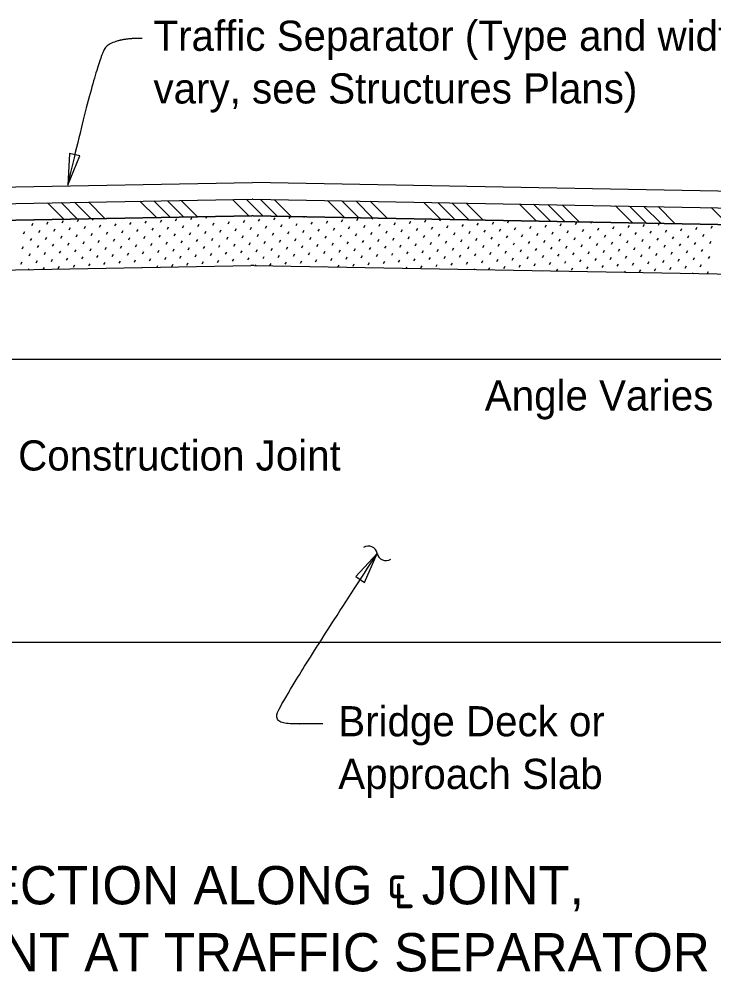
# Model space of a CAD drawing. Extents: x -7.9 to 27, y -3.1 to 14.6.
# Drawn here: x 7.115 to 8.858, y 7.064 to 9.452 of the extents above; entities that cross this region are included whole.
import ezdxf

# ---------------------------------------------------------------- set-up
doc = ezdxf.new("R2010")
doc.units = 0
for name, color, linetype in [('Border', 7, 'Continuous'), ('Patterning', 7, 'Continuous'), ('PlotBorder_dp', 7, 'Continuous'), ('SupstrConc_h', 7, 'Continuous'), ('TextMisc', 7, 'Continuous')]:
    doc.layers.add(name, color=color, linetype=linetype)

msp = doc.modelspace()

# ---------------------------------------------------------------- linework, layer by layer
at = {"layer": 'Patterning'}
for p, q in [((6.7193, 9.0243), (7.7, 9.0424)), ((9.1446, 9.0156), (7.7, 9.0424)), ((5.2585, 7.8906), (10.1444, 7.8906))]:
    msp.add_line(p, q, dxfattribs=at)
at = {"layer": 'PlotBorder_dp'}
for points in [[(7.2366, 9.0361), (7.2671, 9.1092), (7.2413, 9.1152)], [(8.013, 8.1128), (7.9591, 8.0547), (7.9813, 8.0402)]]:
    msp.add_lwpolyline(points, close=True, dxfattribs=at)
for centre, start, end in [((7.9909, 8.1087), 10.958, 122.6852), ((8.0347, 8.1172), 190.958, 302.6852)]:
    msp.add_arc(centre, 0.0224, start, end, dxfattribs=at)
for points in [[(7.4236, 9.4037), (7.3532, 9.4037), (7.3114, 9.3597), (7.2366, 9.0362)], [(7.8761, 7.6857), (7.8344, 7.6857), (7.7607, 7.6857), (7.7607, 7.7274), (8.013, 8.1128)]]:
    msp.add_open_spline(points, degree=2, dxfattribs=at)
at = {"layer": 'SupstrConc_h'}
msp.add_lwpolyline([(9.1821, 8.599), (5.5686, 8.599)], dxfattribs=at)
at = {"layer": 'TextMisc'}
for p, q in [((6.2769, 8.9744), (7.6992, 9.0007)), ((7.1861, 8.9912), (7.227, 8.9503)), ((7.2204, 8.9919), (7.2614, 8.9509)), ((7.2548, 8.9925), (7.2957, 8.9515)), ((7.2892, 8.9931), (7.3301, 8.9522)), ((7.4179, 8.9955), (7.4589, 8.9546)), ((7.4523, 8.9962), (7.4932, 8.9552)), ((7.4866, 8.9968), (7.5276, 8.9558)), ((7.521, 8.9974), (7.5619, 8.9565)), ((7.6498, 8.9998), (7.6907, 8.9589)), ((7.6841, 9.0004), (7.726, 8.9586)), ((7.7008, 9.0007), (9.1231, 8.9744)), ((7.7192, 9.0004), (7.7617, 8.9579)), ((7.7548, 8.9997), (7.7973, 8.9572)), ((7.8885, 8.9972), (7.931, 8.9548)), ((7.9241, 8.9966), (7.9666, 8.9541)), ((7.9598, 8.9959), (8.0023, 8.9534)), ((7.9954, 8.9953), (8.0379, 8.9528)), ((8.1291, 8.9928), (8.1716, 8.9503)), ((8.1647, 8.9921), (8.2072, 8.9496)), ((8.2004, 8.9915), (8.2429, 8.949)), ((8.236, 8.9908), (8.2785, 8.9483)), ((8.3697, 8.9883), (8.4122, 8.9458)), ((8.4053, 8.9877), (8.4478, 8.9452)), ((8.441, 8.987), (8.4835, 8.9445)), ((8.4767, 8.9863), (8.5191, 8.9439)), ((8.6103, 8.9839), (8.6528, 8.9414)), ((8.6459, 8.9832), (8.6884, 8.9407)), ((8.6816, 8.9826), (8.7241, 8.9401)), ((8.7173, 8.9819), (8.7597, 8.9394)), ((7.6985, 8.959), (6.2985, 8.9331)), ((6.2985, 8.9331), (7.6985, 8.959)), ((7.5836, 8.953), (7.5858, 8.9569)), ((7.6217, 8.9563), (7.6225, 8.9576)), ((9.1015, 8.9331), (7.7015, 8.959)), ((7.7015, 8.959), (9.1015, 8.9331)), ((7.7918, 8.9518), (7.795, 8.9573)), ((7.83, 8.955), (7.8309, 8.9566)), ((8.8509, 8.9794), (8.8934, 8.9369)), ((7.1464, 8.9348), (7.1497, 8.9404)), ((7.1846, 8.9381), (7.1878, 8.9437)), ((7.2227, 8.9413), (7.226, 8.9469)), ((7.2609, 8.9446), (7.2641, 8.9502)), ((7.2783, 8.9271), (7.2816, 8.9327)), ((7.299, 8.9478), (7.3013, 8.9516)), ((7.3165, 8.9303), (7.3197, 8.9359)), ((7.3372, 8.951), (7.3379, 8.9523)), ((7.3547, 8.9336), (7.3579, 8.9392)), ((7.3928, 8.9368), (7.3961, 8.9424)), ((7.431, 8.9401), (7.4342, 8.9457)), ((7.4691, 8.9433), (7.4724, 8.9489)), ((7.5073, 8.9465), (7.5105, 8.9521)), ((7.5247, 8.9291), (7.528, 8.9347)), ((7.5454, 8.9498), (7.5487, 8.9554)), ((7.5629, 8.9323), (7.5661, 8.9379)), ((7.601, 8.9356), (7.6043, 8.9412)), ((7.6392, 8.9388), (7.6424, 8.9444)), ((7.6773, 8.9421), (7.6806, 8.9476)), ((7.7155, 8.9453), (7.7187, 8.9509)), ((7.733, 8.9278), (7.7362, 8.9334)), ((7.7537, 8.9485), (7.7569, 8.9541)), ((7.7711, 8.9311), (7.7744, 8.9367)), ((7.8093, 8.9343), (7.8125, 8.9399)), ((7.8474, 8.9376), (7.8507, 8.9432)), ((7.8856, 8.9408), (7.8888, 8.9464)), ((7.9237, 8.944), (7.927, 8.9496)), ((7.9619, 8.9473), (7.9651, 8.9529)), ((7.9793, 8.9298), (7.9826, 8.9354)), ((8, 8.9505), (8.0017, 8.9534)), ((8.0175, 8.9331), (8.0207, 8.9387)), ((8.0557, 8.9363), (8.0589, 8.9419)), ((8.0938, 8.9395), (8.097, 8.9451)), ((8.132, 8.9428), (8.1352, 8.9484)), ((8.1701, 8.946), (8.1726, 8.9503)), ((8.1876, 8.9286), (8.1908, 8.9342)), ((8.2083, 8.9493), (8.2085, 8.9496)), ((8.2257, 8.9318), (8.229, 8.9374)), ((8.2639, 8.9351), (8.2671, 8.9407)), ((8.302, 8.9383), (8.3053, 8.9439)), ((8.3402, 8.9415), (8.3434, 8.9471)), ((8.3783, 8.9448), (8.3793, 8.9464)), ((8.3958, 8.9273), (8.399, 8.9329)), ((8.434, 8.9306), (8.4372, 8.9362)), ((8.4721, 8.9338), (8.4753, 8.9394)), ((8.5103, 8.937), (8.5135, 8.9426)), ((8.5484, 8.9403), (8.5501, 8.9433)), ((8.6422, 8.9293), (8.6454, 8.9349)), ((8.6803, 8.9325), (8.6836, 8.9381)), ((8.7185, 8.9358), (8.721, 8.9401)), ((8.7566, 8.939), (8.7569, 8.9394)), ((8.8504, 8.9281), (8.8536, 8.9337)), ((7.1257, 8.9141), (7.129, 8.9197)), ((7.1639, 8.9174), (7.1671, 8.923)), ((7.202, 8.9206), (7.2053, 8.9262)), ((7.2195, 8.9032), (7.2227, 8.9088)), ((7.2402, 8.9239), (7.2434, 8.9295)), ((7.2577, 8.9064), (7.2609, 8.912)), ((7.2958, 8.9096), (7.299, 8.9152)), ((7.334, 8.9129), (7.3372, 8.9185)), ((7.3721, 8.9161), (7.3754, 8.9217)), ((7.4103, 8.9194), (7.4135, 8.925)), ((7.4484, 8.9226), (7.4517, 8.9282)), ((7.4659, 8.9051), (7.4691, 8.9107)), ((7.4866, 8.9258), (7.4898, 8.9314)), ((7.504, 8.9084), (7.5073, 8.914)), ((7.5422, 8.9116), (7.5454, 8.9172)), ((7.5803, 8.9149), (7.5836, 8.9205)), ((7.6185, 8.9181), (7.6217, 8.9237)), ((7.6567, 8.9214), (7.6599, 8.927)), ((7.6741, 8.9039), (7.6773, 8.9095)), ((7.6948, 8.9246), (7.698, 8.9302)), ((7.7123, 8.9071), (7.7155, 8.9127)), ((7.7504, 8.9104), (7.7537, 8.916)), ((7.7886, 8.9136), (7.7918, 8.9192)), ((7.8267, 8.9169), (7.83, 8.9225)), ((7.8649, 8.9201), (7.8681, 8.9257)), ((7.903, 8.9233), (7.9063, 8.9289)), ((7.9205, 8.9059), (7.9237, 8.9115)), ((7.9412, 8.9266), (7.9444, 8.9322)), ((7.9586, 8.9091), (7.9619, 8.9147)), ((7.9968, 8.9124), (8, 8.918)), ((8.035, 8.9156), (8.0382, 8.9212)), ((8.0731, 8.9188), (8.0763, 8.9244)), ((8.1113, 8.9221), (8.1145, 8.9277)), ((8.1287, 8.9046), (8.132, 8.9102)), ((8.1494, 8.9253), (8.1527, 8.9309)), ((8.1669, 8.9079), (8.1701, 8.9135)), ((8.205, 8.9111), (8.2083, 8.9167)), ((8.2432, 8.9144), (8.2464, 8.92)), ((8.2813, 8.9176), (8.2846, 8.9232)), ((8.3195, 8.9208), (8.3227, 8.9264)), ((8.3369, 8.9034), (8.3402, 8.909)), ((8.3576, 8.9241), (8.3609, 8.9297)), ((8.3751, 8.9066), (8.3783, 8.9122)), ((8.4133, 8.9099), (8.4165, 8.9155)), ((8.4514, 8.9131), (8.4546, 8.9187)), ((8.4896, 8.9163), (8.4928, 8.9219)), ((8.5277, 8.9196), (8.531, 8.9252)), ((8.5659, 8.9228), (8.5691, 8.9284)), ((8.5833, 8.9054), (8.5866, 8.911)), ((8.604, 8.9261), (8.6073, 8.9317)), ((8.6215, 8.9086), (8.6247, 8.9142)), ((8.6596, 8.9119), (8.6629, 8.9174)), ((8.6978, 8.9151), (8.701, 8.9207)), ((8.7359, 8.9183), (8.7392, 8.9239)), ((8.7741, 8.9216), (8.7773, 8.9272)), ((8.7916, 8.9041), (8.7948, 8.9097)), ((8.8123, 8.9248), (8.8155, 8.9304)), ((8.8297, 8.9074), (8.833, 8.913)), ((7.1432, 8.8967), (7.1464, 8.9023)), ((7.1606, 8.8792), (7.1639, 8.8848)), ((7.1813, 8.8999), (7.1846, 8.9055)), ((7.1988, 8.8825), (7.202, 8.8881)), ((7.237, 8.8857), (7.2402, 8.8913)), ((7.2751, 8.8889), (7.2783, 8.8945)), ((7.3133, 8.8922), (7.3165, 8.8978)), ((7.3514, 8.8954), (7.3547, 8.901)), ((7.3896, 8.8987), (7.3928, 8.9043)), ((7.407, 8.8812), (7.4103, 8.8868)), ((7.4277, 8.9019), (7.431, 8.9075)), ((7.4452, 8.8845), (7.4484, 8.89)), ((7.4833, 8.8877), (7.4866, 8.8933)), ((7.5215, 8.8909), (7.5247, 8.8965)), ((7.5596, 8.8942), (7.5629, 8.8998)), ((7.5978, 8.8974), (7.601, 8.903)), ((7.6153, 8.88), (7.6185, 8.8856)), ((7.636, 8.9007), (7.6392, 8.9063)), ((7.6534, 8.8832), (7.6567, 8.8888)), ((7.6916, 8.8864), (7.6948, 8.892)), ((7.7297, 8.8897), (7.733, 8.8953)), ((7.7679, 8.8929), (7.7711, 8.8985)), ((7.806, 8.8962), (7.8093, 8.9018)), ((7.8442, 8.8994), (7.8474, 8.905)), ((7.8616, 8.8819), (7.8649, 8.8875)), ((7.8823, 8.9026), (7.8856, 8.9082)), ((7.8998, 8.8852), (7.903, 8.8908)), ((7.9379, 8.8884), (7.9412, 8.894)), ((7.9761, 8.8917), (7.9793, 8.8973)), ((8.0143, 8.8949), (8.0175, 8.9005)), ((8.0524, 8.8982), (8.0557, 8.9037)), ((8.0699, 8.8807), (8.0731, 8.8863)), ((8.0906, 8.9014), (8.0938, 8.907)), ((8.108, 8.8839), (8.1113, 8.8895)), ((8.1462, 8.8872), (8.1494, 8.8928)), ((8.1843, 8.8904), (8.1876, 8.896)), ((8.2225, 8.8937), (8.2257, 8.8993)), ((8.2606, 8.8969), (8.2639, 8.9025)), ((8.2781, 8.8794), (8.2813, 8.885)), ((8.2988, 8.9001), (8.302, 8.9057)), ((8.3162, 8.8827), (8.3195, 8.8883)), ((8.3544, 8.8859), (8.3576, 8.8915)), ((8.3926, 8.8892), (8.3958, 8.8948)), ((8.4307, 8.8924), (8.434, 8.898)), ((8.4689, 8.8956), (8.4721, 8.9012)), ((8.507, 8.8989), (8.5103, 8.9045)), ((8.5245, 8.8814), (8.5277, 8.887)), ((8.5452, 8.9021), (8.5484, 8.9077)), ((8.5626, 8.8847), (8.5659, 8.8903)), ((8.6008, 8.8879), (8.604, 8.8935)), ((8.6389, 8.8912), (8.6422, 8.8968)), ((8.6771, 8.8944), (8.6803, 8.9)), ((8.7152, 8.8976), (8.7185, 8.9032)), ((8.7327, 8.8802), (8.7359, 8.8858)), ((8.7534, 8.9009), (8.7566, 8.9065)), ((8.7709, 8.8834), (8.7741, 8.889)), ((8.809, 8.8867), (8.8123, 8.8923)), ((8.8472, 8.8899), (8.8504, 8.8955)), ((7.1225, 8.876), (7.1257, 8.8816)), ((7.1399, 8.8585), (7.1432, 8.8641)), ((7.1781, 8.8618), (7.1813, 8.8674)), ((7.2163, 8.865), (7.2195, 8.8706)), ((7.2544, 8.8682), (7.2577, 8.8738)), ((7.2926, 8.8715), (7.2958, 8.8771)), ((7.3307, 8.8747), (7.334, 8.8803)), ((7.3482, 8.8573), (7.3514, 8.8629)), ((7.3689, 8.878), (7.3721, 8.8836)), ((7.3863, 8.8605), (7.3896, 8.8661)), ((7.4245, 8.8638), (7.4277, 8.8694)), ((7.4626, 8.867), (7.4659, 8.8726)), ((7.5008, 8.8702), (7.504, 8.8758)), ((7.5389, 8.8735), (7.5422, 8.8791)), ((7.5564, 8.856), (7.5596, 8.8616)), ((7.5771, 8.8767), (7.5803, 8.8823)), ((7.5946, 8.8593), (7.5978, 8.8649)), ((7.6327, 8.8625), (7.636, 8.8681)), ((7.6709, 8.8657), (7.6741, 8.8713)), ((7.709, 8.869), (7.7123, 8.8746)), ((7.7472, 8.8722), (7.7504, 8.8778)), ((7.7853, 8.8755), (7.7886, 8.8811)), ((7.8028, 8.858), (7.806, 8.8636)), ((7.8235, 8.8787), (7.8267, 8.8843)), ((7.8409, 8.8612), (7.8442, 8.8668)), ((7.8791, 8.8645), (7.8823, 8.8701)), ((7.9172, 8.8677), (7.9205, 8.8733)), ((7.9554, 8.871), (7.9586, 8.8766)), ((7.9936, 8.8742), (7.9968, 8.8798)), ((8.011, 8.8568), (8.0143, 8.8624)), ((8.0317, 8.8775), (8.035, 8.8831)), ((8.0492, 8.86), (8.0524, 8.8656)), ((8.0873, 8.8632), (8.0906, 8.8688)), ((8.1255, 8.8665), (8.1287, 8.8721)), ((8.1636, 8.8697), (8.1669, 8.8753)), ((8.2018, 8.873), (8.205, 8.8786)), ((8.2192, 8.8555), (8.2225, 8.8611)), ((8.2399, 8.8762), (8.2432, 8.8818)), ((8.2574, 8.8587), (8.2606, 8.8643)), ((8.2956, 8.862), (8.2988, 8.8676)), ((8.3337, 8.8652), (8.3369, 8.8708)), ((8.3719, 8.8685), (8.3751, 8.8741)), ((8.41, 8.8717), (8.4133, 8.8773)), ((8.4482, 8.8749), (8.4514, 8.8805)), ((8.4656, 8.8575), (8.4689, 8.8631)), ((8.4863, 8.8782), (8.4896, 8.8838)), ((8.5038, 8.8607), (8.507, 8.8663)), ((8.5419, 8.864), (8.5452, 8.8696)), ((8.5801, 8.8672), (8.5833, 8.8728)), ((8.6182, 8.8705), (8.6215, 8.8761)), ((8.6564, 8.8737), (8.6596, 8.8793)), ((8.6739, 8.8562), (8.6771, 8.8618)), ((8.6946, 8.8769), (8.6978, 8.8825)), ((8.712, 8.8595), (8.7152, 8.8651)), ((8.7502, 8.8627), (8.7534, 8.8683)), ((8.7883, 8.866), (8.7916, 8.8716)), ((8.8265, 8.8692), (8.8297, 8.8748)), ((7.1192, 8.8378), (7.1225, 8.8434)), ((7.1574, 8.8411), (7.1606, 8.8467)), ((7.1956, 8.8443), (7.1988, 8.8499)), ((7.2337, 8.8475), (7.237, 8.8531)), ((7.2719, 8.8508), (7.2751, 8.8564)), ((7.2893, 8.8333), (7.2926, 8.8389)), ((7.31, 8.854), (7.3133, 8.8596)), ((7.3275, 8.8366), (7.3307, 8.8422)), ((7.3656, 8.8398), (7.3689, 8.8454)), ((7.4038, 8.8431), (7.407, 8.8487)), ((7.4419, 8.8463), (7.4452, 8.8519)), ((7.4801, 8.8495), (7.4833, 8.8551)), ((7.4976, 8.8321), (7.5008, 8.8377)), ((7.5182, 8.8528), (7.5215, 8.8584)), ((7.5357, 8.8353), (7.5389, 8.8409)), ((7.5739, 8.8386), (7.5771, 8.8442)), ((7.612, 8.8418), (7.6153, 8.8474)), ((7.6502, 8.845), (7.6534, 8.8506)), ((7.6883, 8.8483), (7.6916, 8.8539)), ((7.7265, 8.8515), (7.7297, 8.8571)), ((7.7439, 8.8341), (7.7472, 8.8397)), ((7.7646, 8.8548), (7.7679, 8.8604)), ((7.7821, 8.8373), (7.7853, 8.8429)), ((7.8202, 8.8406), (7.8235, 8.8462)), ((7.8584, 8.8438), (7.8616, 8.8494)), ((7.8966, 8.847), (7.8998, 8.8526)), ((7.9347, 8.8503), (7.9379, 8.8559)), ((7.9522, 8.8328), (7.9554, 8.8384)), ((7.9729, 8.8535), (7.9761, 8.8591)), ((7.9903, 8.8361), (7.9936, 8.8417)), ((8.0285, 8.8393), (8.0317, 8.8449)), ((8.0666, 8.8425), (8.0699, 8.8481)), ((8.1048, 8.8458), (8.108, 8.8514)), ((8.1429, 8.849), (8.1462, 8.8546)), ((8.1604, 8.8316), (8.1636, 8.8372)), ((8.1811, 8.8523), (8.1843, 8.8579)), ((8.1985, 8.8348), (8.2018, 8.8404)), ((8.2367, 8.838), (8.2399, 8.8436)), ((8.2749, 8.8413), (8.2781, 8.8469)), ((8.313, 8.8445), (8.3162, 8.8501)), ((8.3512, 8.8478), (8.3544, 8.8534)), ((8.3893, 8.851), (8.3926, 8.8566)), ((8.4068, 8.8336), (8.41, 8.8392)), ((8.4275, 8.8543), (8.4307, 8.8599)), ((8.4449, 8.8368), (8.4482, 8.8424)), ((8.4831, 8.84), (8.4863, 8.8456)), ((8.5212, 8.8433), (8.5245, 8.8489)), ((8.5594, 8.8465), (8.5626, 8.8521)), ((8.5975, 8.8498), (8.6008, 8.8554)), ((8.615, 8.8323), (8.6182, 8.8379)), ((8.6357, 8.853), (8.6389, 8.8586)), ((8.6532, 8.8355), (8.6564, 8.8411)), ((8.6913, 8.8388), (8.6946, 8.8444)), ((8.7295, 8.842), (8.7327, 8.8476)), ((8.7676, 8.8453), (8.7709, 8.8509)), ((8.8058, 8.8485), (8.809, 8.8541)), ((8.8439, 8.8517), (8.8472, 8.8573)), ((7.6961, 8.8339), (6.3631, 8.8092)), ((7.1386, 8.8236), (7.1399, 8.826)), ((7.1753, 8.8243), (7.1781, 8.8292)), ((7.213, 8.8269), (7.2163, 8.8324)), ((7.2512, 8.8301), (7.2544, 8.8357)), ((7.4231, 8.8289), (7.4245, 8.8312)), ((7.4598, 8.8296), (7.4626, 8.8344)), ((9.0369, 8.8092), (7.7039, 8.8339)), ((7.7075, 8.8339), (7.709, 8.8364)), ((7.8784, 8.8307), (7.8791, 8.8319)), ((7.9143, 8.83), (7.9172, 8.8352)), ((8.0851, 8.8269), (8.0873, 8.8307)), ((8.1222, 8.8283), (8.1255, 8.8339)), ((8.256, 8.8237), (8.2574, 8.8262)), ((8.2923, 8.8238), (8.2956, 8.8294)), ((8.3305, 8.8271), (8.3337, 8.8327)), ((8.3686, 8.8303), (8.3719, 8.8359)), ((8.4268, 8.8205), (8.4275, 8.8217)), ((8.4627, 8.8199), (8.4656, 8.8249)), ((8.5005, 8.8226), (8.5038, 8.8282)), ((8.5387, 8.8258), (8.5419, 8.8314)), ((8.5768, 8.8291), (8.5801, 8.8347)), ((8.6335, 8.8167), (8.6357, 8.8204)), ((8.6706, 8.8181), (8.6739, 8.8237)), ((8.7088, 8.8213), (8.712, 8.8269)), ((8.7469, 8.8246), (8.7502, 8.8302)), ((8.7851, 8.8278), (8.7883, 8.8334)), ((8.8044, 8.8135), (8.8058, 8.816)), ((8.8232, 8.8311), (8.8265, 8.8366)), ((8.8407, 8.8136), (8.8439, 8.8192))]:
    msp.add_line(p, q, dxfattribs=at)
for centre, radius in [((7.7, 8.959), 0.0417), ((7.7, 8.8757), 0.0833), ((7.7, 8.6257), 0.2083)]:
    msp.add_arc(centre, radius, 88.9384, 91.0616, dxfattribs=at)

# ---------------------------------------------------------------- texts
at = {"layer": 'Border'}
for s, p in [('Angle Varies', (8.2828, 8.4709)), ('Construction Joint', (7.1124, 8.3205))]:
    msp.add_text(s, height=0.0756, dxfattribs=at).set_placement(p)
at = {"layer": 'PlotBorder_dp'}
for s, height, p in [('Traffic Separator (Type and width ', 0.0756, (7.4518, 9.3724)), ('vary, see Structures Plans)', 0.0756, (7.4518, 9.2404)), ('Bridge Deck or ', 0.0756, (7.9152, 7.6543)), ('Approach Slab ', 0.0756, (7.9152, 7.5223)), ('PARTIAL SECTION ALONG ℄ JOINT,', 0.096, (6.3749, 7.2331)), ('JOINT TREATMENT AT TRAFFIC SEPARATOR', 0.096, (6.0513, 7.0651))]:
    msp.add_text(s, height=height, dxfattribs=at).set_placement(p)

doc.saveas('drawing.dxf')
